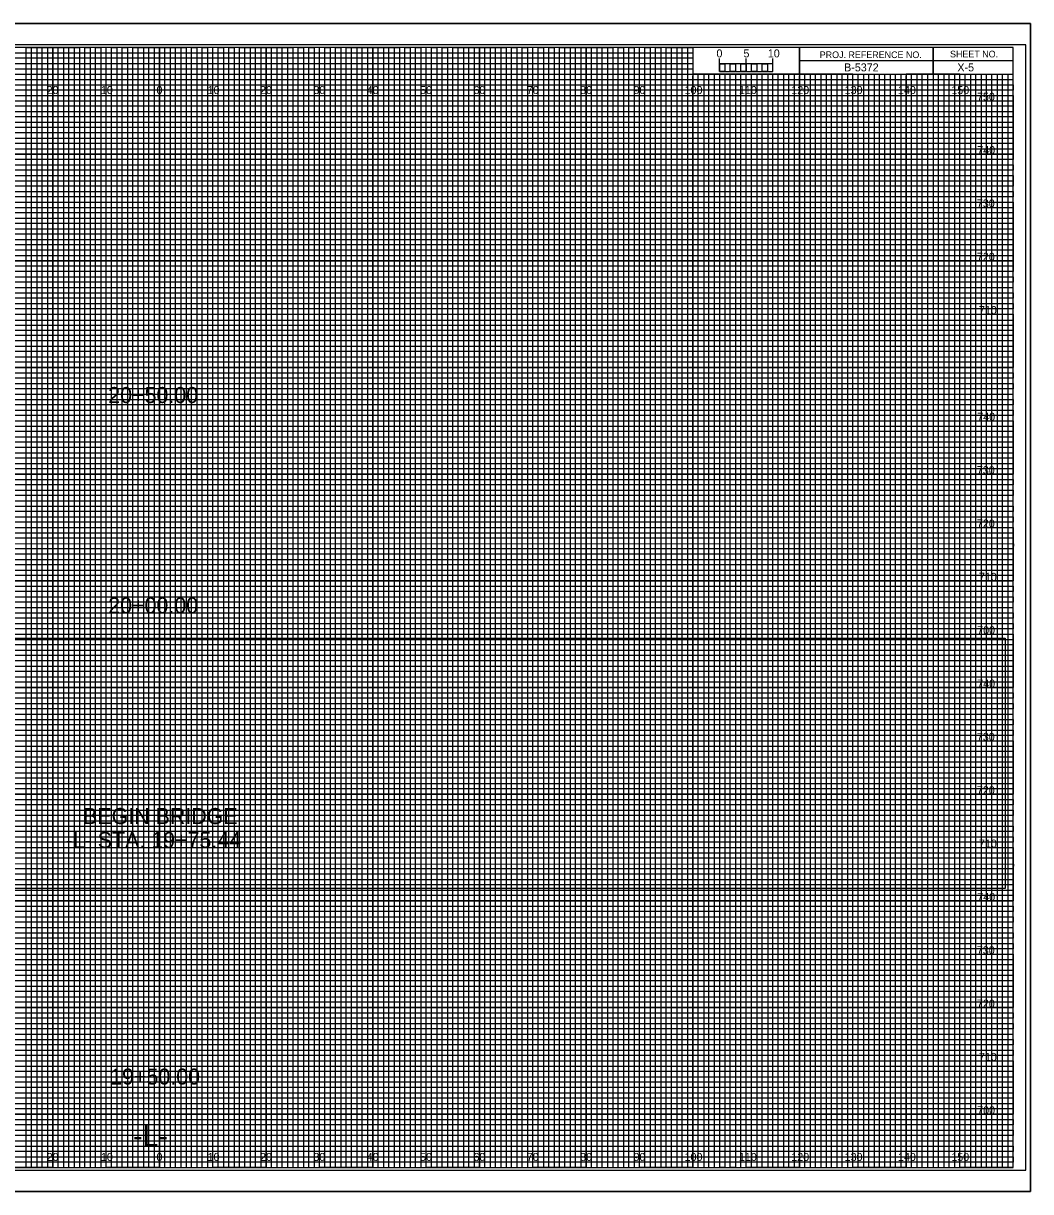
# Model space of a CAD drawing. Extents: x -98 to 717, y -10 to 1974.
# Drawn here: x 134.5 to 323.3, y 875.5 to 1094.5 of the extents above; entities that cross this region are included whole.
import ezdxf

# ---------------------------------------------------------------- set-up
doc = ezdxf.new("R2010")
doc.units = 0
for name, color, linetype in [('Default', 7, 'Continuous'), ('Exist XS Center Line Elevation Label', 7, 'Continuous'), ('Prop CMT Conc Surface', 7, 'Continuous'), ('Prop CMT Concrete Structures', 7, 'Continuous'), ('Prop CMT Pvmt Course 1', 7, 'Continuous'), ('Prop CMT Pvmt Course 1 CG', 7, 'Continuous'), ('Prop CMT Pvmt Course 2', 7, 'Continuous'), ('Prop CMT Pvmt Course 3', 7, 'Continuous'), ('Prop CMT Pvmt Surface', 7, 'Continuous'), ('Prop CMT Pvmt Surface Shoulder', 7, 'Continuous'), ('Prop CMT Shld Paved Course 1', 7, 'Continuous'), ('Prop CMT Shld Paved Course 2', 7, 'Continuous'), ('Prop CMT Shld Paved Course 3', 7, 'Continuous'), ('Prop CMT Slope Grass', 7, 'Continuous'), ('Prop CMT Subgrade Earthwork', 7, 'Continuous'), ('Prop XS Ditch Standard Text', 7, 'Continuous'), ('Prop XS Earthwork Shape', 7, 'Continuous'), ('Prop XS Elevation Labels', 7, 'Continuous'), ('Typical Curb CELL', 7, 'Continuous')]:
    doc.layers.add(name, color=color, linetype=linetype)

msp = doc.modelspace()

# ---------------------------------------------------------------- linework, layer by layer
at = {"layer": 'Default'}
msp.add_lwpolyline([(323.3, 875.5), (-13.4, 875.5), (-13.4, 1094.5), (323.3, 1094.5)], close=True, dxfattribs=at)
at = {"layer": 'Exist XS Center Line Elevation Label'}
for p, q in [((0, 1089), (260, 1089)), ((260, 1089), (260, 1087.98)), ((260, 1087.98), (0, 1087.98)), ((0, 1087), (260, 1087)), ((260, 1087), (260, 1085.89)), ((260, 1085.89), (0, 1085.89)), ((0, 1084), (320, 1084))]:
    msp.add_line(p, q, dxfattribs=at)
for points in [[(0, 1083), (270, 1083), (320, 1083), (320, 1082), (0, 1082)], [(0, 1081), (320, 1081), (320, 1079), (0, 1079)], [(0, 1078), (320, 1078), (320, 1077), (0, 1076.98)], [(0, 1076), (320, 1076), (320, 1074), (0, 1074)], [(0, 1073), (320, 1073), (320, 1072), (0, 1072)], [(0, 1071), (320, 1071), (320, 1069), (0, 1069)], [(0, 1068), (320, 1068), (320, 1067), (0, 1067)], [(0, 1066), (320, 1066), (320, 1064), (0, 1064)], [(0, 1063), (320, 1063), (320, 1062), (0, 1062)], [(0, 1061), (320, 1061), (320, 1059), (0, 1059)], [(0, 1058), (320, 1058), (320, 1057), (0, 1057)], [(0, 1056), (320, 1056), (320, 1053.95), (320, 1053), (320, 1052), (0, 1052)], [(0, 1054), (320, 1054), (320, 1053), (0, 1053)], [(0, 1051), (320, 1051), (320, 1049), (0, 1049.03)], [(0, 1049.03), (320, 1049), (320, 1048), (0, 1048)], [(0, 1047), (320, 1047), (320, 1046), (0, 1046)], [(0, 1044), (320, 1044), (320, 1043), (0, 1043)], [(0, 1042), (320, 1042), (320, 1041), (0, 1041)], [(-0.07, 1038.89), (320, 1038.89), (320, 1037.88), (-0.07, 1037.88)], [(0, 1037), (320, 1037), (320, 1036), (0, 1036)], [(0, 1034), (320, 1034), (320, 1033), (0, 1033)], [(0, 1032), (320, 1032), (320, 1031), (0, 1031)], [(0, 1029), (320, 1029), (320, 1028), (0, 1028)], [(0, 1027), (320, 1027), (320, 1026), (0, 1026)], [(0, 1024), (320, 1024), (320, 1023), (0, 1023)], [(0, 1022), (320, 1022), (320, 1021), (0, 1021)], [(0, 1019), (320, 1019), (319.99, 1017.98), (0, 1018)], [(0, 1017), (320, 1017), (320, 1016), (0, 1016)], [(0, 1014), (320, 1014), (320, 1013), (0, 1013)], [(0, 1012), (320, 1012), (320, 1011), (0, 1011)], [(0, 1009), (320, 1009), (320, 1008), (0, 1008)], [(0, 1007), (320, 1007), (320, 1006), (0, 1006)], [(0, 1004), (320, 1004), (320, 1003), (0, 1003)], [(0, 1002), (320, 1002), (320, 1001), (0, 1001)], [(0, 999), (320, 999), (320, 998), (0, 998)], [(0, 996.99), (320.07, 996.91), (320, 996), (0, 996)], [(0, 994), (320, 994), (320, 993), (0, 993)], [(0, 992), (320, 992), (320, 991), (0, 991)], [(0, 989), (320, 989), (320, 988), (0, 988)], [(0, 987), (320, 987), (320, 986), (0, 986)], [(0, 984), (320, 984), (320, 983), (0, 983)], [(0, 982), (320, 982), (320, 981), (0, 981)], [(0, 979), (320, 979), (320, 978), (0, 978)], [(0, 977), (320, 977), (320, 976), (0, 976)], [(0, 974), (320, 974), (320, 973), (0, 973)], [(0, 972), (320, 972), (320, 971), (0, 971)], [(0, 969), (320, 969), (320, 968), (0, 968)], [(0, 967), (320, 967), (320, 966), (0, 966)], [(0, 964), (320, 964), (320, 963), (0, 963)], [(0, 962), (320, 962), (320, 961), (0, 961)], [(0, 959), (320, 959), (319.99, 957.98), (0, 958)], [(0, 957), (320, 957), (320, 956), (0, 956)], [(0, 954), (320, 954), (320, 953), (0, 953)], [(0, 952), (320, 952), (320, 951), (0, 951)], [(0, 949), (320, 949), (320, 948), (0, 948)], [(0, 947), (320, 947), (320, 946), (0, 946)], [(0, 944), (320, 944), (320, 943), (0, 943)], [(0, 942), (320, 942), (320, 941), (0, 941)], [(0, 939), (320, 939), (320, 938), (0, 938)], [(0, 936.99), (320.07, 936.91), (320, 936), (0, 936)], [(0, 934), (320, 934), (320, 933), (0, 933)], [(0, 932), (320, 932), (320, 931), (0, 931)], [(0, 929), (320, 929), (320, 928), (0, 928)], [(0, 927), (320, 927), (320, 926), (0, 926)], [(0, 924), (320, 924), (320, 923), (0, 923)], [(0, 922), (320, 922), (320, 921), (0, 921)], [(0, 919), (320, 919), (320, 918), (0, 918)], [(0, 917), (320, 917), (320, 916), (0, 916)], [(0, 914), (320, 914), (320, 913), (0, 913)], [(0, 912), (320, 912), (320, 911), (0, 911)], [(0, 909), (320, 909), (320, 908), (0, 908)], [(0, 907), (320, 907), (320, 906), (0, 906)], [(0, 904), (320, 904), (320, 903), (0, 903)], [(0, 902), (320, 902), (320, 901), (0, 901)], [(0, 899), (320, 899), (320, 898), (0, 898)], [(0, 897), (320, 897), (320, 896), (0, 896)], [(0, 894), (320, 894), (320, 893), (0, 893)], [(0, 892), (320, 892), (320, 891), (0, 891)], [(0, 889), (320, 889), (320, 888), (0, 888)], [(0, 887), (320, 887), (320, 886), (0, 886)], [(0, 884), (320, 884), (320, 883), (0, 883)], [(0, 882), (320, 882), (320, 881), (0, 881)]]:
    msp.add_lwpolyline(points, dxfattribs=at)
at = {"layer": 'Prop CMT Conc Surface'}
for p, q in [((305, 1090), (305, 1085)), ((305, 1085), (305, 1090)), ((280, 1087.5), (280, 1085)), ((320, 1087.49), (280, 1087.49)), ((280, 1085), (320, 1085))]:
    msp.add_line(p, q, dxfattribs=at)
for points in [[(320, 1090), (0, 1090), (0, 880), (320, 880)], [(280, 1090), (260, 1090), (260, 1085.03), (280, 1085.03)], [(320, 1090), (280, 1090), (280, 1085), (320, 1085)]]:
    msp.add_lwpolyline(points, close=True, dxfattribs=at)
at = {"layer": 'Prop CMT Concrete Structures'}
for p, q in [((140, 880), (140, 1090)), ((150, 880), (150, 1090)), ((160, 880), (160, 1090)), ((170, 880), (170, 1090)), ((180, 880), (180, 1090)), ((190, 880), (190, 1090)), ((200, 880), (200, 1090)), ((210, 880), (210, 1090)), ((220, 880), (220, 1090)), ((230, 880), (230, 1090)), ((240, 880), (240, 1090)), ((250, 880), (250, 1090)), ((260, 880), (260, 1084.69)), ((270, 880), (270, 1084.69)), ((280, 880), (280, 1084.69)), ((290, 880), (290, 1084.69)), ((300, 880), (300, 1084.69)), ((310, 880), (310, 1084.69)), ((0, 1080), (320, 1080)), ((0, 1070), (320, 1070)), ((0, 1060), (320, 1060)), ((0, 1050), (320, 1050)), ((0, 1040), (320, 1040)), ((0, 1030), (320, 1030)), ((0, 1020), (320, 1020)), ((0, 1010), (320, 1010)), ((0, 1000), (320, 1000)), ((0, 990), (320, 990)), ((0, 980), (320, 980)), ((0, 970), (320, 970)), ((0, 960), (320, 960)), ((0, 950), (320, 950)), ((0, 940), (320, 940)), ((0, 930), (320, 930)), ((0, 920), (320, 920)), ((0, 910), (320, 910)), ((0, 900), (320, 900)), ((0, 890), (320, 890))]:
    msp.add_line(p, q, dxfattribs=at)
at = {"layer": 'Prop CMT Pvmt Course 2'}
msp.add_lwpolyline([(-13.4, 875.5), (323.3, 875.5), (323.3, 1094.5), (-13.4, 1094.5)], close=True, dxfattribs=at)
at = {"layer": 'Prop CMT Pvmt Course 3'}
msp.add_lwpolyline([(-10.8, 879.5), (322.4, 879.5), (322.4, 1090.5), (-10.8, 1090.5)], close=True, dxfattribs=at)
at = {"layer": 'Prop CMT Pvmt Surface'}
for p, q in [((323.3, 1094.5), (-13.4, 1094.5)), ((-13.4, 875.5), (323.3, 875.5))]:
    msp.add_line(p, q, dxfattribs=at)
at = {"layer": 'Prop CMT Slope Grass'}
for p, q in [((265, 1085.49), (265, 1087.9)), ((265, 1086.9), (265, 1087.9)), ((270, 1085.49), (270, 1087.9)), ((275, 1085.49), (275, 1087.9)), ((275, 1086.9), (275, 1087.9))]:
    msp.add_line(p, q, dxfattribs=at)
for points in [[(275, 1086.9), (265, 1086.9), (265, 1085.49), (275, 1085.49)], [(265, 1086.9), (266, 1086.9), (266, 1085.49), (265, 1085.49)], [(267, 1086.9), (268, 1086.9), (268, 1085.49), (267, 1085.49)], [(269, 1086.9), (270, 1086.9), (270, 1085.49), (269, 1085.49)], [(271, 1086.9), (272, 1086.9), (272, 1085.49), (271, 1085.49)], [(273, 1086.9), (274, 1086.9), (274, 1085.49), (273, 1085.49)]]:
    msp.add_lwpolyline(points, close=True, dxfattribs=at)
at = {"layer": 'Prop CMT Subgrade Earthwork'}
for p, q in [((267, 1085), (266.01, 1085)), ((266.01, 1085), (266.01, 880)), ((267, 880), (267, 1085)), ((269, 1085), (268, 1085)), ((268, 1085), (268, 880)), ((269, 880), (269, 1085)), ((266.01, 880), (265, 880)), ((268, 880), (267, 880))]:
    msp.add_line(p, q, dxfattribs=at)
for points in [[(135, 880), (136, 880), (136, 1090), (137, 1090), (137, 880)], [(137, 880), (138, 880), (138, 1090), (139, 1090), (139, 880)], [(140, 880), (141, 880), (141, 1090), (142, 1090), (142, 880)], [(142, 880), (143, 880), (143, 1090), (144, 1090), (144, 880)], [(145, 880), (146, 880), (146, 1090), (147, 1090), (147, 880)], [(147, 880), (148, 880), (148, 1090), (149, 1090), (149, 880)], [(150, 880), (151, 880), (151, 1090), (152, 1090), (152, 880)], [(152, 880), (153, 880), (153, 1090), (154, 1090), (154, 880)], [(155, 880), (156, 880), (156, 1090), (157, 1090), (157, 880)], [(157, 880), (158, 880), (158, 1090), (159, 1090), (159, 880)], [(160, 880), (161, 880), (161, 1090), (162, 1090), (162, 880)], [(162, 880), (163, 880), (163, 1090), (164, 1090), (164, 880)], [(165, 880), (166, 880), (166, 1090), (167, 1090), (167, 880)], [(167, 880), (168, 880), (168, 1090), (169, 1090), (169, 880)], [(170, 880), (171, 880), (171, 1090), (172, 1090), (172, 880)], [(172, 880), (173, 880), (173, 1090), (174, 1090), (174, 880)], [(175, 880), (176, 880), (176, 1090), (177, 1090), (177, 880)], [(177, 880), (178, 880), (178, 1090), (179, 1090), (179, 880)], [(180, 880), (181, 880), (181, 1090), (182, 1090), (182, 880)], [(182, 880), (183, 880), (183, 1090), (184, 1090), (184, 880)], [(185, 880), (186, 880), (186, 1090), (187, 1090), (187, 880)], [(187, 880), (188, 880), (188, 1090), (189, 1090), (189, 880)], [(190, 880), (191, 880), (191, 1090), (192, 1090), (192, 880)], [(192, 880), (193, 880), (193, 1090), (194, 1090), (194, 880)], [(195, 880), (196, 880), (196, 1090), (197, 1090), (197, 880)], [(197, 880), (198, 880), (198, 1090), (199, 1090), (199, 880)], [(200, 880), (201, 880), (201, 1090), (202, 1090), (202, 880)], [(202, 880), (203, 880), (203, 1090), (204, 1090), (204, 880)], [(205, 880), (206, 880), (206, 1090), (207, 1090), (207, 880)], [(207, 880), (208, 880), (208, 1090), (209, 1090), (209, 880)], [(210, 880), (211, 880), (211, 1090), (212, 1090), (212, 880)], [(212, 880), (213, 880), (213, 1090), (214, 1090), (214, 880)], [(215, 880), (216, 880), (216, 1090), (217, 1090), (217, 880)], [(217, 880), (218, 880), (218, 1090), (219, 1090), (219, 880)], [(220, 880), (221, 880), (221, 1090), (222, 1090), (222, 880)], [(222, 880), (223, 880), (223, 1090), (224, 1090), (224, 880)], [(225, 880), (226, 880), (226, 1090), (227, 1090), (227, 880)], [(227, 880), (228, 880), (228, 1090), (229, 1090), (229, 880)], [(230, 880), (231, 880), (231, 1090), (232, 1090), (232, 880)], [(232, 880), (233, 880), (233, 1090), (234, 1090), (234, 880)], [(235, 880), (236, 880), (236, 1090), (237, 1090), (237, 880)], [(237, 880), (238, 880), (238, 1090), (239, 1090), (239, 880)], [(240, 880), (241, 880), (241, 1090), (242, 1090), (242, 880)], [(242, 880), (243, 880), (243, 1090), (244, 1090), (244, 880)], [(245, 880), (246, 880), (246, 1090), (247, 1090), (247, 880)], [(247, 880), (248, 880), (248, 1090), (249, 1090), (249, 880)], [(250, 880), (251, 880), (251, 1090), (252, 1090), (252, 880)], [(252, 880), (253, 880), (253, 1090), (254, 1090), (254, 880)], [(255, 880), (256, 880), (256, 1090), (257, 1090), (257, 880)], [(257, 880), (258, 880), (258, 1090), (259, 1090), (259, 880)], [(260, 880), (261, 880), (261, 1085), (262.02, 1085), (262.02, 880)], [(262, 880), (263, 880), (263, 1085), (263.99, 1085), (263.99, 880)], [(270, 880), (270.98, 880), (270.98, 1085), (272, 1085), (272, 880)], [(272, 880), (273, 880), (273, 1085), (274.05, 1085), (274.05, 880)], [(275, 880), (276, 880), (276, 1085), (277, 1085), (277, 880)], [(277, 880), (278, 880), (278, 1085), (279, 1085), (279, 880)], [(280, 880), (281, 880), (281, 1085), (282, 1085), (282, 880)], [(282, 880), (283, 880), (283, 1085), (284, 1085), (284, 880)], [(285, 880), (286, 880), (286, 1085), (287, 1085), (287, 880)], [(287, 880), (288, 880), (288, 1085), (289, 1085), (289, 880)], [(290, 880), (291, 880), (291, 1085), (292, 1085), (292, 880)], [(292, 880), (293, 880), (293, 1085), (294, 1085), (294, 880)], [(295, 880), (296, 880), (296, 1085), (297, 1085), (297, 880)], [(297, 880), (298, 880), (298, 1085), (299, 1085), (299, 880)], [(300, 880), (301, 880), (301, 1085), (302, 1085), (302, 880)], [(302, 880), (303, 880), (303, 1085), (304, 1085), (304, 880)], [(305, 880), (306, 880), (306, 1085), (307, 1085), (307, 880)], [(307, 880), (308, 880), (308, 1085), (309, 1085), (309, 880)], [(310, 880), (311, 880), (311, 1085), (312, 1085), (312, 880)], [(312, 880), (313, 880), (313, 1085), (314, 1085), (314, 880)], [(315, 880), (316, 880), (316, 1085), (317, 1085), (317, 880)], [(317, 880), (318, 880), (318, 1085), (319, 1085), (319, 880)]]:
    msp.add_lwpolyline(points, dxfattribs=at)
at = {"layer": 'Prop XS Ditch Standard Text'}
msp.add_lwpolyline([(7.42, 979.26), (318.51, 979.26), (318.51, 932.35), (7.42, 932.35)], close=True, dxfattribs=at)
at = {"layer": 'Prop XS Elevation Labels'}
for p, q in [((150, 1090), (140, 1090)), ((140, 1090), (140, 880)), ((150, 880), (150, 1090)), ((170, 1090), (160, 1090)), ((160, 1090), (160, 880)), ((170, 880), (170, 1090)), ((190, 1090), (180, 1090)), ((180, 1090), (180, 880)), ((190, 880), (190, 1090)), ((210, 1090), (200, 1090)), ((200, 1090), (200, 880)), ((210, 880), (210, 1090)), ((230, 1090), (220, 1090)), ((220, 1090), (220, 880)), ((230, 880), (230, 1090)), ((250, 1090), (240, 1090)), ((240, 1090), (240, 880)), ((250, 880), (250, 1090)), ((260, 1090), (260, 880)), ((270, 880), (270, 1085)), ((290, 1085), (280, 1085)), ((280, 1085), (280, 880)), ((290, 880), (290, 1085)), ((310, 1085), (300, 1085)), ((300, 1085), (300, 880)), ((310, 880), (310, 1085)), ((140, 880), (130, 880)), ((160, 880), (150, 880)), ((180, 880), (170, 880)), ((200, 880), (190, 880)), ((220, 880), (210, 880)), ((240, 880), (230, 880)), ((260, 880), (250, 880)), ((280, 880), (270, 880)), ((300, 880), (290, 880)), ((320, 880), (310, 880)), ((320, 880), (320, 880))]:
    msp.add_line(p, q, dxfattribs=at)
for points in [[(0, 1080), (320, 1080), (320, 1070), (0, 1070)], [(0, 1060), (320, 1060), (320, 1050), (0, 1050)], [(0, 1040), (320, 1040), (320, 1030), (0, 1030)], [(0, 1020), (320, 1020), (320, 1010), (0, 1010)], [(0, 1000), (320, 1000), (320, 990), (0, 990)], [(0, 980), (320, 980), (320, 970), (0, 970)], [(0, 960), (320, 960), (320, 950), (0, 950)], [(0, 940), (320, 940), (320, 930), (0, 930)], [(0, 920), (320, 920), (320, 910), (0, 910)], [(0, 900), (320, 900), (320, 890), (0, 890)]]:
    msp.add_lwpolyline(points, dxfattribs=at)
at = {"layer": 'Typical Curb CELL'}
for points in [[(125, 880), (135, 880), (135, 1090), (145, 1090), (145, 880), (155, 880), (155, 1090), (165, 1090), (165, 880), (175, 880), (175, 1090), (185, 1090), (185, 880), (195, 880), (195, 1090), (205, 1090), (205, 880), (215, 880), (215, 1090), (225, 1090), (225, 880), (235, 880), (235, 1090), (245, 1090), (245, 880), (255, 880), (255, 1090), (259.93, 1090), (260, 1090), (260, 1085), (264.99, 1085), (264.99, 880), (275, 880), (275, 1085), (285, 1085), (285, 880), (295, 880), (295, 1085), (305, 1085), (305, 880), (315, 880), (315, 1085)], [(0, 1085), (275, 1085)], [(0, 1065), (320, 1065), (320, 1075), (0, 1075)], [(0, 1045), (320, 1045), (320, 1055), (0, 1055)], [(0, 1025), (320, 1025), (320, 1035), (0, 1035)], [(0, 1005), (320, 1005), (320, 1015), (0, 1015)], [(0, 985), (320, 985), (320, 995), (0, 995)], [(0, 965), (320, 965), (320, 975), (0, 975)], [(0, 945), (320, 945), (320, 955), (0, 955)], [(0, 925), (320, 925), (320, 935), (0, 935)], [(0, 905), (320, 905), (320, 915), (0, 915)], [(0, 885), (320, 885), (320, 895), (0, 895)]]:
    msp.add_lwpolyline(points, dxfattribs=at)

# ---------------------------------------------------------------- texts
at = {"layer": 'Prop CMT Conc Surface'}
for s, p in [('PROJ. REFERENCE NO.', (283.77, 1087.99)), ('SHEET NO.', (308.19, 1088.12))]:
    msp.add_text(s, height=1.25, dxfattribs=at).set_placement(p)
at = {"layer": 'Prop CMT Pvmt Course 1'}
for s, p in [('20+50.00', (150.41, 1023.33)), ('20+00.00', (150.41, 983.9)), ('BEGIN BRIDGE', (145.69, 944.41)), ('-L- STA. 19+75.44', (142.42, 939.91)), ('19+50.00', (150.77, 895.57))]:
    msp.add_text(s, height=3, dxfattribs=at).set_placement(p)
at = {"layer": 'Prop CMT Pvmt Course 1 CG'}
for s, p in [('750', (313.25, 1080)), ('740', (313.3, 1070)), ('730', (313.22, 1060)), ('720', (313.23, 1050)), ('710', (313.61, 1040)), ('740', (313.3, 1020)), ('730', (313.22, 1010)), ('720', (313.23, 1000)), ('710', (313.61, 990)), ('700', (313.28, 980)), ('740', (313.3, 970)), ('730', (313.22, 960)), ('720', (313.23, 950)), ('710', (313.61, 940)), ('740', (313.3, 930)), ('730', (313.22, 920)), ('720', (313.23, 910)), ('710', (313.61, 900)), ('700', (313.28, 890))]:
    msp.add_text(s, height=1.5, dxfattribs=at).set_placement(p)
at = {"layer": 'Prop CMT Pvmt Surface Shoulder'}
for s, p in [('5', (269.47, 1088.12)), ('10', (274.04, 1088.12))]:
    msp.add_text(s, height=1.5, dxfattribs=at).set_placement(p)
at = {"layer": 'Prop CMT Shld Paved Course 1'}
msp.add_text('X-5', height=1.5, dxfattribs=at).set_placement((309.57, 1085.5))
at = {"layer": 'Prop CMT Shld Paved Course 2'}
msp.add_text('B-5372', height=1.5, dxfattribs=at).set_placement((288.34, 1085.5))
at = {"layer": 'Prop CMT Shld Paved Course 3'}
msp.add_text('-L-', height=4, dxfattribs=at).set_placement((155.06, 884))
at = {"layer": 'Prop CMT Slope Grass'}
msp.add_text('0', height=1.5, dxfattribs=at).set_placement((264.41, 1088.12))
at = {"layer": 'Prop XS Earthwork Shape'}
for s, p in [('20', (138.86, 1081.25)), ('10', (149.04, 1081.25)), ('0', (159.45, 1081.25)), ('0', (159.45, 1081.25)), ('10', (169.04, 1081.25)), ('20', (178.86, 1081.25)), ('30', (188.86, 1081.25)), ('40', (198.86, 1081.25)), ('50', (208.86, 1081.25)), ('60', (218.86, 1081.25)), ('70', (228.86, 1081.25)), ('80', (238.86, 1081.25)), ('90', (248.86, 1081.25)), ('100', (258.44, 1081.25)), ('110', (268.62, 1081.25)), ('120', (278.44, 1081.25)), ('130', (288.44, 1081.25)), ('140', (298.44, 1081.25)), ('150', (308.44, 1081.25)), ('20', (138.86, 881.25)), ('10', (149.04, 881.25)), ('0', (159.45, 881.25)), ('0', (159.45, 881.25)), ('10', (169.04, 881.25)), ('20', (178.86, 881.25)), ('30', (188.86, 881.25)), ('40', (198.86, 881.25)), ('50', (208.86, 881.25)), ('60', (218.86, 881.25)), ('70', (228.86, 881.25)), ('80', (238.86, 881.25)), ('90', (248.86, 881.25)), ('100', (258.44, 881.25)), ('110', (268.62, 881.25)), ('120', (278.44, 881.25)), ('130', (288.44, 881.25)), ('140', (298.44, 881.25)), ('150', (308.44, 881.25))]:
    msp.add_text(s, height=1.5, dxfattribs=at).set_placement(p)

doc.saveas('drawing.dxf')
